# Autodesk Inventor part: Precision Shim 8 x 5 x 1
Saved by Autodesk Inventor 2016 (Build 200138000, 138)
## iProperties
Created: 2015-11
Part Number: Precision Shim 8 x 5 x 1
Material: Generic
Document SubType Name: Modeling
Designer: John
Density: 1 g/cm^3
Appearance: Default
Author: John
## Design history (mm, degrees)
feature "SOLID1"
body "Solid1"
